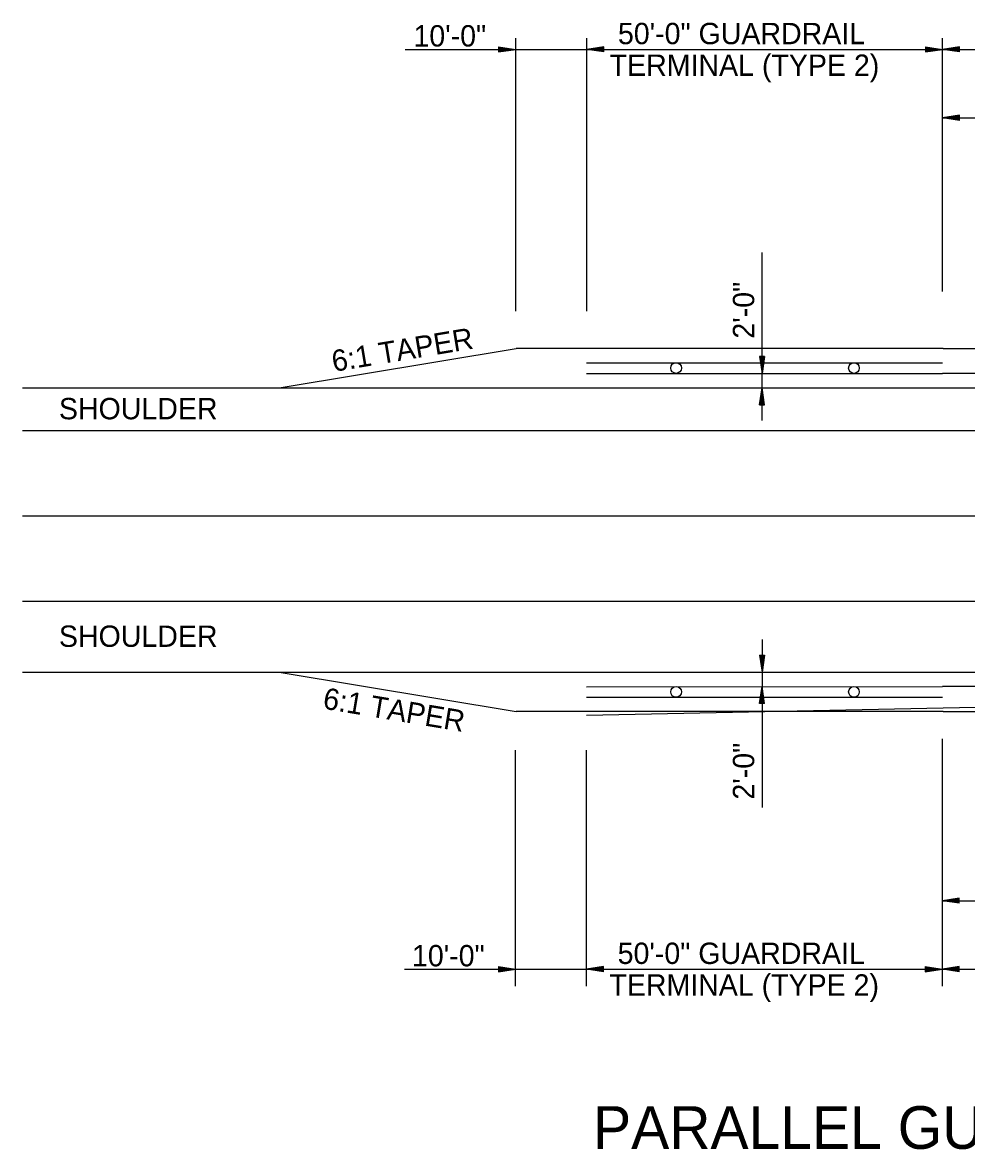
# Model space of a CAD drawing. Extents: x 1373853 to 1374003, y 380191 to 380927.
# Drawn here: x 1373877.32 to 1373903.85, y 380872.58 to 380904.25 of the extents above; entities that cross this region are included whole.
import ezdxf

# ---------------------------------------------------------------- set-up
doc = ezdxf.new("R2010")
doc.units = 0
for name, color, linetype in [('2', 7, 'Continuous'), ('44', 7, 'Continuous'), ('7', 7, 'Continuous'), ('8', 7, 'Continuous'), ('R_Proposed Road', 7, 'Continuous')]:
    doc.layers.add(name, color=color, linetype=linetype)

msp = doc.modelspace()

# ---------------------------------------------------------------- linework, layer by layer
at = {"layer": '2'}
for p, q in [((1373891.184, 380896.14), (1373891.184, 380903.815)), ((1373893.184, 380896.14), (1373893.184, 380903.815)), ((1373903.184, 380896.693), (1373903.184, 380903.815)), ((1373888.075, 380903.499), (1373962.85, 380903.499)), ((1373903.184, 380901.577), (1373965.149, 380901.575)), ((1373898.109, 380893.067), (1373898.109, 380897.788)), ((1373898.109, 380886.914), (1373898.109, 380882.193)), ((1373903.176, 380877.168), (1373903.176, 380884.12)), ((1373891.176, 380877.168), (1373891.176, 380883.805)), ((1373893.176, 380877.168), (1373893.176, 380883.805)), ((1373903.176, 380879.572), (1373967.577, 380879.572)), ((1373888.057, 380877.648), (1373962.85, 380877.648))]:
    msp.add_line(p, q, dxfattribs=at)
at = {"layer": '44'}
for p, q in [((1373877.32, 380893.991), (1373970.938, 380893.991)), ((1373877.32, 380885.991), (1373970.938, 380885.991))]:
    msp.add_line(p, q, dxfattribs=at)
at = {"layer": '7'}
for p, q in [((1373890.704, 380903.571), (1373891.184, 380903.499)), ((1373890.704, 380903.571), (1373890.704, 380903.427)), ((1373890.704, 380903.559), (1373891.102, 380903.499)), ((1373890.704, 380903.547), (1373891.019, 380903.499)), ((1373890.704, 380903.535), (1373890.94, 380903.499)), ((1373890.704, 380903.523), (1373890.861, 380903.499)), ((1373890.704, 380903.511), (1373890.78, 380903.499)), ((1373890.704, 380903.427), (1373891.184, 380903.499)), ((1373890.704, 380903.475), (1373890.861, 380903.499)), ((1373890.704, 380903.451), (1373891.019, 380903.499)), ((1373890.704, 380903.439), (1373891.102, 380903.499)), ((1373890.704, 380903.463), (1373890.94, 380903.499)), ((1373890.704, 380903.487), (1373890.78, 380903.499)), ((1373893.661, 380903.573), (1373893.184, 380903.501)), ((1373893.661, 380903.43), (1373893.184, 380903.501)), ((1373893.661, 380903.561), (1373893.262, 380903.501)), ((1373893.661, 380903.442), (1373893.262, 380903.501)), ((1373893.661, 380903.549), (1373893.346, 380903.501)), ((1373893.661, 380903.454), (1373893.346, 380903.501)), ((1373893.661, 380903.537), (1373893.427, 380903.501)), ((1373893.661, 380903.466), (1373893.427, 380903.501)), ((1373893.661, 380903.525), (1373893.506, 380903.501)), ((1373893.661, 380903.478), (1373893.506, 380903.501)), ((1373893.661, 380903.511), (1373893.587, 380903.501)), ((1373893.661, 380903.489), (1373893.587, 380903.501)), ((1373893.661, 380903.43), (1373893.661, 380903.573)), ((1373902.704, 380903.573), (1373903.184, 380903.501)), ((1373902.704, 380903.573), (1373902.704, 380903.43)), ((1373902.704, 380903.561), (1373903.102, 380903.501)), ((1373902.704, 380903.549), (1373903.019, 380903.501)), ((1373902.704, 380903.537), (1373902.94, 380903.501)), ((1373902.704, 380903.525), (1373902.861, 380903.501)), ((1373902.704, 380903.513), (1373902.78, 380903.501)), ((1373902.704, 380903.43), (1373903.184, 380903.501)), ((1373902.704, 380903.478), (1373902.861, 380903.501)), ((1373902.704, 380903.454), (1373903.019, 380903.501)), ((1373902.704, 380903.442), (1373903.102, 380903.501)), ((1373902.704, 380903.466), (1373902.94, 380903.501)), ((1373902.704, 380903.489), (1373902.78, 380903.501)), ((1373903.661, 380903.573), (1373903.184, 380903.501)), ((1373903.661, 380903.43), (1373903.184, 380903.501)), ((1373903.661, 380903.561), (1373903.262, 380903.501)), ((1373903.661, 380903.442), (1373903.262, 380903.501)), ((1373903.661, 380903.549), (1373903.346, 380903.501)), ((1373903.661, 380903.454), (1373903.346, 380903.501)), ((1373903.661, 380903.537), (1373903.427, 380903.501)), ((1373903.661, 380903.466), (1373903.427, 380903.501)), ((1373903.661, 380903.525), (1373903.506, 380903.501)), ((1373903.661, 380903.478), (1373903.506, 380903.501)), ((1373903.661, 380903.511), (1373903.587, 380903.501)), ((1373903.661, 380903.489), (1373903.587, 380903.501)), ((1373903.661, 380903.43), (1373903.661, 380903.573)), ((1373903.661, 380901.649), (1373903.184, 380901.577)), ((1373903.661, 380901.505), (1373903.184, 380901.577)), ((1373903.661, 380901.637), (1373903.262, 380901.577)), ((1373903.661, 380901.517), (1373903.262, 380901.577)), ((1373903.661, 380901.625), (1373903.346, 380901.577)), ((1373903.661, 380901.529), (1373903.346, 380901.577)), ((1373903.661, 380901.613), (1373903.427, 380901.577)), ((1373903.661, 380901.541), (1373903.427, 380901.577)), ((1373903.661, 380901.601), (1373903.506, 380901.577)), ((1373903.661, 380901.553), (1373903.506, 380901.577)), ((1373903.661, 380901.587), (1373903.587, 380901.577)), ((1373903.661, 380901.565), (1373903.587, 380901.577)), ((1373903.661, 380901.505), (1373903.661, 380901.649)), ((1373898.038, 380894.871), (1373898.109, 380894.391)), ((1373898.181, 380894.871), (1373898.038, 380894.871)), ((1373898.05, 380894.871), (1373898.109, 380894.472)), ((1373898.062, 380894.871), (1373898.109, 380894.553)), ((1373898.074, 380894.871), (1373898.109, 380894.634)), ((1373898.086, 380894.871), (1373898.109, 380894.715)), ((1373898.097, 380894.871), (1373898.109, 380894.794)), ((1373898.181, 380894.871), (1373898.109, 380894.391)), ((1373898.133, 380894.871), (1373898.109, 380894.715)), ((1373898.157, 380894.871), (1373898.109, 380894.553)), ((1373898.169, 380894.871), (1373898.109, 380894.472)), ((1373898.145, 380894.871), (1373898.109, 380894.634)), ((1373898.121, 380894.871), (1373898.109, 380894.794)), ((1373898.035, 380893.511), (1373898.109, 380893.991)), ((1373898.05, 380893.511), (1373898.109, 380893.909)), ((1373898.181, 380893.511), (1373898.109, 380893.991)), ((1373898.169, 380893.511), (1373898.109, 380893.909)), ((1373898.062, 380893.511), (1373898.109, 380893.828)), ((1373898.074, 380893.511), (1373898.109, 380893.747)), ((1373898.086, 380893.511), (1373898.109, 380893.668)), ((1373898.097, 380893.511), (1373898.109, 380893.587)), ((1373898.155, 380893.511), (1373898.109, 380893.828)), ((1373898.145, 380893.511), (1373898.109, 380893.747)), ((1373898.131, 380893.511), (1373898.109, 380893.668)), ((1373898.119, 380893.511), (1373898.109, 380893.587)), ((1373898.035, 380893.511), (1373898.181, 380893.511)), ((1373898.035, 380886.471), (1373898.109, 380885.991)), ((1373898.035, 380886.471), (1373898.181, 380886.471)), ((1373898.05, 380886.471), (1373898.109, 380886.072)), ((1373898.062, 380886.471), (1373898.109, 380886.153)), ((1373898.074, 380886.471), (1373898.109, 380886.234)), ((1373898.086, 380886.471), (1373898.109, 380886.313)), ((1373898.097, 380886.471), (1373898.109, 380886.394)), ((1373898.181, 380886.471), (1373898.109, 380885.991)), ((1373898.131, 380886.471), (1373898.109, 380886.313)), ((1373898.155, 380886.471), (1373898.109, 380886.153)), ((1373898.169, 380886.471), (1373898.109, 380886.072)), ((1373898.145, 380886.471), (1373898.109, 380886.234)), ((1373898.119, 380886.471), (1373898.109, 380886.394)), ((1373898.038, 380885.111), (1373898.109, 380885.591)), ((1373898.05, 380885.111), (1373898.109, 380885.509)), ((1373898.062, 380885.111), (1373898.109, 380885.428)), ((1373898.074, 380885.111), (1373898.109, 380885.347)), ((1373898.181, 380885.111), (1373898.109, 380885.591)), ((1373898.169, 380885.111), (1373898.109, 380885.509)), ((1373898.157, 380885.111), (1373898.109, 380885.428)), ((1373898.145, 380885.111), (1373898.109, 380885.347)), ((1373898.181, 380885.111), (1373898.038, 380885.111)), ((1373898.086, 380885.111), (1373898.109, 380885.266)), ((1373898.097, 380885.111), (1373898.109, 380885.187)), ((1373898.133, 380885.111), (1373898.109, 380885.266)), ((1373898.121, 380885.111), (1373898.109, 380885.187)), ((1373903.653, 380879.644), (1373903.176, 380879.572)), ((1373903.653, 380879.632), (1373903.254, 380879.572)), ((1373903.653, 380879.62), (1373903.338, 380879.572)), ((1373903.653, 380879.5), (1373903.653, 380879.644)), ((1373903.653, 380879.5), (1373903.176, 380879.572)), ((1373903.653, 380879.512), (1373903.254, 380879.572)), ((1373903.653, 380879.524), (1373903.338, 380879.572)), ((1373903.653, 380879.608), (1373903.419, 380879.572)), ((1373903.653, 380879.536), (1373903.419, 380879.572)), ((1373903.653, 380879.596), (1373903.498, 380879.572)), ((1373903.653, 380879.548), (1373903.498, 380879.572)), ((1373903.653, 380879.582), (1373903.579, 380879.572)), ((1373903.653, 380879.56), (1373903.579, 380879.572)), ((1373890.696, 380877.719), (1373891.176, 380877.648)), ((1373890.696, 380877.719), (1373890.696, 380877.576)), ((1373893.653, 380877.719), (1373893.176, 380877.648)), ((1373893.653, 380877.576), (1373893.653, 380877.719)), ((1373902.696, 380877.719), (1373903.176, 380877.648)), ((1373902.696, 380877.719), (1373902.696, 380877.576)), ((1373903.653, 380877.719), (1373903.176, 380877.648)), ((1373903.653, 380877.576), (1373903.653, 380877.719)), ((1373890.696, 380877.707), (1373891.094, 380877.648)), ((1373890.696, 380877.695), (1373891.011, 380877.648)), ((1373890.696, 380877.683), (1373890.932, 380877.648)), ((1373890.696, 380877.671), (1373890.853, 380877.648)), ((1373890.696, 380877.66), (1373890.772, 380877.648)), ((1373890.696, 380877.576), (1373891.176, 380877.648)), ((1373890.696, 380877.624), (1373890.853, 380877.648)), ((1373890.696, 380877.6), (1373891.011, 380877.648)), ((1373890.696, 380877.588), (1373891.094, 380877.648)), ((1373890.696, 380877.612), (1373890.932, 380877.648)), ((1373890.696, 380877.636), (1373890.772, 380877.648)), ((1373893.653, 380877.576), (1373893.176, 380877.648)), ((1373893.653, 380877.707), (1373893.254, 380877.648)), ((1373893.653, 380877.588), (1373893.254, 380877.648)), ((1373893.653, 380877.695), (1373893.338, 380877.648)), ((1373893.653, 380877.6), (1373893.338, 380877.648)), ((1373893.653, 380877.683), (1373893.419, 380877.648)), ((1373893.653, 380877.612), (1373893.419, 380877.648)), ((1373893.653, 380877.671), (1373893.498, 380877.648)), ((1373893.653, 380877.624), (1373893.498, 380877.648)), ((1373893.653, 380877.657), (1373893.579, 380877.648)), ((1373893.653, 380877.636), (1373893.579, 380877.648)), ((1373902.696, 380877.707), (1373903.094, 380877.648)), ((1373902.696, 380877.695), (1373903.011, 380877.648)), ((1373902.696, 380877.683), (1373902.932, 380877.648)), ((1373902.696, 380877.671), (1373902.853, 380877.648)), ((1373902.696, 380877.66), (1373902.772, 380877.648)), ((1373902.696, 380877.576), (1373903.176, 380877.648)), ((1373902.696, 380877.624), (1373902.853, 380877.648)), ((1373902.696, 380877.6), (1373903.011, 380877.648)), ((1373902.696, 380877.588), (1373903.094, 380877.648)), ((1373902.696, 380877.612), (1373902.932, 380877.648)), ((1373902.696, 380877.636), (1373902.772, 380877.648)), ((1373903.653, 380877.576), (1373903.176, 380877.648)), ((1373903.653, 380877.707), (1373903.254, 380877.648)), ((1373903.653, 380877.588), (1373903.254, 380877.648)), ((1373903.653, 380877.695), (1373903.338, 380877.648)), ((1373903.653, 380877.6), (1373903.338, 380877.648)), ((1373903.653, 380877.683), (1373903.419, 380877.648)), ((1373903.653, 380877.612), (1373903.419, 380877.648)), ((1373903.653, 380877.671), (1373903.498, 380877.648)), ((1373903.653, 380877.624), (1373903.498, 380877.648)), ((1373903.653, 380877.657), (1373903.579, 380877.648)), ((1373903.653, 380877.636), (1373903.579, 380877.648))]:
    msp.add_line(p, q, dxfattribs=at)
at = {"layer": 'R_Proposed Road'}
for p, q in [((1373884.594, 380893.993), (1373891.194, 380895.093)), ((1373903.196, 380895.091), (1373891.194, 380895.093)), ((1373893.174, 380894.69), (1373903.176, 380894.688)), ((1373893.174, 380894.393), (1373903.176, 380894.391)), ((1373877.32, 380892.791), (1373970.938, 380892.791)), ((1373877.32, 380890.391), (1373970.938, 380890.391)), ((1373877.32, 380887.991), (1373970.938, 380887.991)), ((1373884.594, 380885.988), (1373891.194, 380884.888)), ((1373893.174, 380885.588), (1373903.176, 380885.591)), ((1373893.176, 380884.791), (1373933.176, 380885.591)), ((1373893.174, 380885.291), (1373903.176, 380885.294)), ((1373903.196, 380884.891), (1373891.194, 380884.888))]:
    msp.add_line(p, q, dxfattribs=at)
for points in [[(1373903.196, 380895.091), (1373933.183, 380895.091)], [(1373905.692, 380894.391), (1373903.176, 380894.391)], [(1373905.692, 380885.591), (1373903.176, 380885.591)], [(1373903.196, 380884.891), (1373933.183, 380884.891)]]:
    msp.add_lwpolyline(points, dxfattribs=at)
for centre in [(1373895.692, 380894.543), (1373900.692, 380894.543), (1373895.692, 380885.441), (1373900.692, 380885.441)]:
    msp.add_circle(centre, 0.15, dxfattribs=at)

# ---------------------------------------------------------------- texts
at = {"layer": '2'}
for s, rotation, p in [('10\'-0"', 0, (1373888.309, 380903.581)), ('50\'-0" GUARDRAIL', 0, (1373894.057, 380903.646)), ('TERMINAL (TYPE 2)', 0, (1373893.825, 380902.756)), ('2\'-0"', 90, (1373897.888, 380895.37)), ('6:1 TAPER', 9.4623, (1373886.066, 380894.434)), ('SHOULDER', 0, (1373878.343, 380893.103)), ('SHOULDER', 0, (1373878.343, 380886.707)), ('6:1 TAPER', 350.5377, (1373885.738, 380884.975)), ('2\'-0"', 90, (1373897.888, 380882.414)), ('50\'-0" GUARDRAIL', 0, (1373894.049, 380877.794)), ('10\'-0"', 0, (1373888.268, 380877.727)), ('TERMINAL (TYPE 2)', 0, (1373893.817, 380876.904))]:
    msp.add_text(s, height=0.6, rotation=rotation, dxfattribs=at).set_placement(p)
at = {"layer": '8'}
msp.add_text('PARALLEL GUARDRAIL INSTALLATION FOR OVERHEAD SIGN STRUCTURES', height=1.2, rotation=0, dxfattribs=at).set_placement((1373893.359, 380872.597))

doc.saveas('drawing.dxf')
